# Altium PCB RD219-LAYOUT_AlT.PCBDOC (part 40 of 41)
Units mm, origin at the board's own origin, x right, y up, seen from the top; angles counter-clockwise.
Board outline 209.75 x 159.97 mm, 2 copper layers (TOP, BOTTOM), stack 0 mm thick; 398 components, 199 nets, 1469 pads, 0 vias.
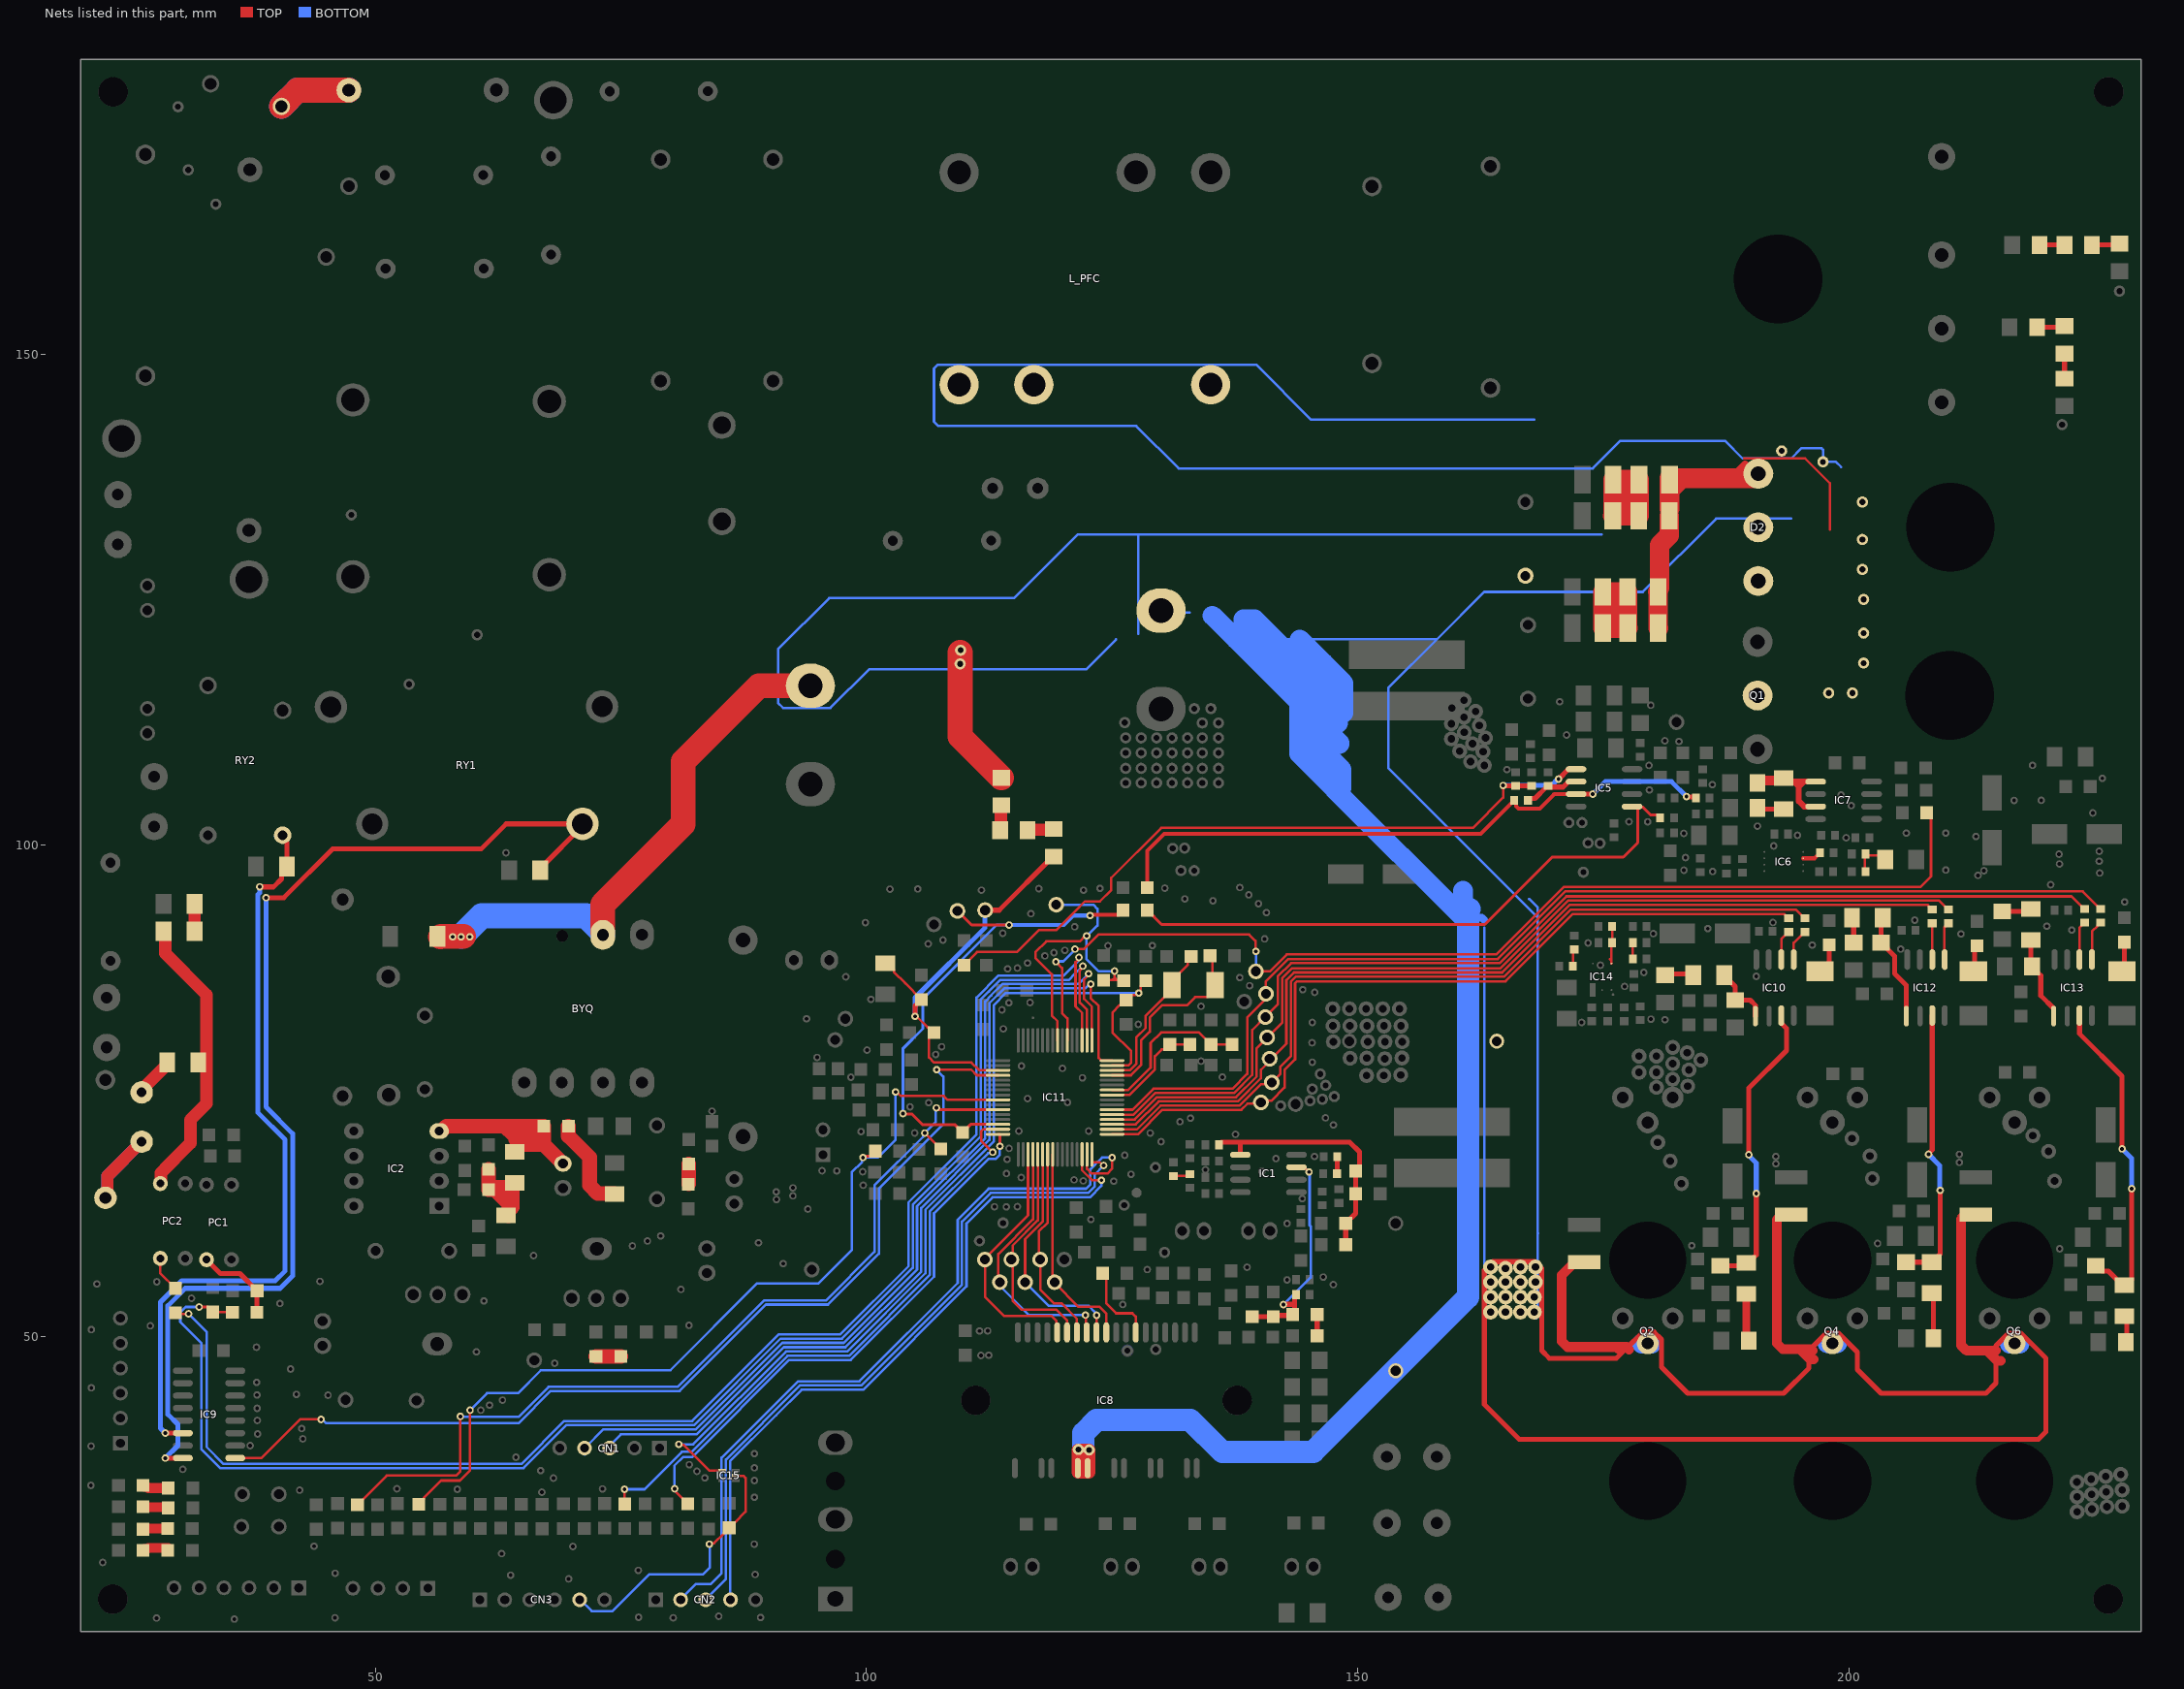
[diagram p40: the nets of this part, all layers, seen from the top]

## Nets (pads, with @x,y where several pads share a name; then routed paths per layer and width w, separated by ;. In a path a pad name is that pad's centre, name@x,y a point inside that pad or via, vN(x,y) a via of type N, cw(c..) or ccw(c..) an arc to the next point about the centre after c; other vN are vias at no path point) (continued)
NetD2_1: D2.1 D2.3 L_PFC.4 L_PFC.5 L_PFC.6 pad.@193.146,140.134 pad.@197.35,139.025 pad.@197.927,115.504 pad.@200.34,115.504 pad.@201.356,128.077 pad.@201.356,131.125 pad.@201.356,134.935 pad.@201.483,118.552 pad.@201.483,121.6 pad.@201.483,125.029 Q1.2 R37.2 R39.2 R94.1 R96.1 | length 208.2
  TOP w0.254: 189.313,139.38 195.514,139.38 198.054,136.84 198.054,132.141
  TOP w0.8: 187.894,137.348 188.021,137.348 189.418,138.745
  TOP w2: R96.1@180.554,125.791 180.567,125.778 180.567,122.121 R94.1@180.58,122.108 ; R96.1@180.704,126.191 180.704,130.539 181.697,131.532 R37.2@181.697,133.538 ; R39.2@181.71,136.117 R39.2@181.723,136.13 ; R37.2@181.723,134.225 R39.2@181.723,136.13 ; R39.2@181.723,137.221 R39.2@181.723,136.13 ; R39.2@181.723,137.348 182.941,137.348 ; 187.894,137.348 182.941,137.348 ; 188.021,137.348 D2.3@190.18,137.348 ; R39.2@181.723,136.13 182.941,137.348
  BOTTOM w0.254: 107.197,142.773 ccw(c107.391,142.936) 107.391,142.682 127.442,142.682 131.76,138.364 173.924,138.364 176.718,141.158 187.386,141.158 189.164,139.38 194.117,139.38 195.133,140.396 197.201,140.396 197.35,140.247 pad.@197.35,139.025 198.663,139.025 199.197,138.491 ; 107.196,142.773 106.868,143.101 106.868,148.524 107.249,148.905 139.678,148.905 145.266,143.317 167.955,143.317
NetD5_2: D5.2 R20.1 | length 9.8
  TOP w1.5: R20.1@69.657,71.435 69.657,70.419 71.816,68.26 71.816,65.402 72.645,64.573 74.306,64.573 D5.2@74.356,64.523
NetD8_2: D8.2 R15.2 R16.1 | length 4.6
  TOP w0.254: R16.1@201.613,97.343 R15.2@201.613,99.121 ; R15.2@201.675,99.121 201.802,98.994 D8.2@203.842,98.994 ; D8.2@203.234,98.127 D8.2@203.677,98.57
NetD11_1: D11.1 R44.2 | length 2.7
  TOP w0.5: R44.2@190.691,103.82 190.818,103.693 D11.1@193.355,103.693
NetD11_2: D11.2 IC7.5 IC7.7 R43.2 | length 11.4
  TOP w0.5: D11.2@193.555,106.849 D11.2@193.867,106.537
  TOP w0.6: D11.2@193.867,106.537 193.917,106.487 194.398,106.487 ; IC7.7@196.601,103.947 195.433,103.947 194.879,104.501 194.879,105.979 ; IC7.5@196.601,106.487 195.387,106.487 ; 194.398,106.487 194.879,106.487 ; 194.398,106.487 194.398,106.46 194.879,105.979 ; 194.879,105.979 195.387,106.487 ; 194.879,105.979 194.879,106.487 ; 194.879,106.487 195.387,106.487
  TOP w1.016: R43.2@190.691,106.36 190.936,106.605 193.111,106.605 D11.2@193.355,106.849
NetD12_1: D12.1 TH1.2 | length 4.4
  TOP w1.27: TH1.2@26.223,74.864 TH1.2@26.223,75.099 ; TH1.2@26.223,75.139 TH1.2@26.223,75.099 ; D12.1@28.836,77.912 28.836,77.712 TH1.2@26.223,75.099
  BOTTOM w1.27: TH1.2@26.223,74.864 TH1.2@26.498,74.864
NetD12_2: D12.2 PC2.C ZD3.2 | length 29.5
  TOP w1.27: PC2.C@28.128,65.593 28.177,65.642 28.177,66.666 28.915,67.416 30.41,68.933 31.176,69.709 31.176,72.07 32.827,73.721 32.827,84.805 28.62,89.012 28.62,91.082 ZD3.2@28.455,91.247
  BOTTOM w1.27: PC2.C@28.128,65.593 PC2.C@28.128,65.696
NetD14_1: D14.1 IC9.14 pad.@28.636,40.193 pad.@38.239,95.779 RY2.4 | length 77.3
  TOP w0.254: IC9.14@30.291,40.066 IC9.14@30.418,40.193
  TOP w0.5: pad.@28.636,40.193 IC9.14@30.418,40.193
  TOP w0.508: pad.@38.239,95.779 39.645,95.779 40.463,96.597 40.463,97.305 D14.1@41.009,97.851 41.009,100.257 40.574,100.692 RY2.4@40.574,101.036
  BOTTOM w0.254: RY2.4@39.812,100.909 RY2.4@39.939,100.909
  BOTTOM w0.5: pad.@28.636,40.193 28.128,40.701 28.128,53.528 30.287,55.687 39.812,55.687 40.828,56.703 40.828,70.038 38.071,72.795 38.071,95.011 38.239,95.179 pad.@38.239,95.779
NetD15_1: D15.1 R90.1 | length 4.3
  TOP w0.508: D15.1@197.038,87.183 D15.1@197.054,87.183 ; D15.1@197.8,87.929 D15.1@197.054,87.183 ; R90.1@197.993,89.861 197.993,87.929 197.247,87.183 D15.1@197.054,87.183
NetD16_1: D16.1 R91.2 | length 4.9
  TOP w0.8: D16.1@189.545,54.363 189.545,49.845 R91.2@189.799,49.591
NetD16_2: D16.2 IC10.7 pad.@189.801,68.519 pad.@190.561,64.577 R120.2 | length 30.5
  TOP w0.508: R120.2@187.005,57.211 D16.2@189.704,57.211 ; D16.2@189.545,57.519 189.745,57.519 190.291,58.065 190.561,58.335 pad.@190.561,64.577 ; pad.@189.801,68.519 189.801,75.293 193.636,79.128 193.636,81.372 193.101,81.907 IC10.7@193.101,82.682
  BOTTOM w0.508: pad.@189.801,68.519 189.801,68.45 190.561,67.69 pad.@190.561,64.577
NetD17_1: D17.1 R122.2 | length 2.9
  TOP w0.508: R122.2@181.29,86.802 181.417,86.929 D17.1@184.157,86.929
NetD17_2: D17.2 IC10.5 R123.2 | length 6.5
  TOP w0.508: D17.2@187.313,86.929 187.313,86.729 D17.2@187.859,86.183 ; D17.2@187.859,86.183 188.402,85.64 R123.2@188.402,84.262 189.926,84.262 190.462,83.726 190.462,82.636 IC10.5@190.466,82.632
NetD18_1: D18.1 R125.1 | length 2.7
  TOP w0.508: D18.1@212.659,87.183 212.786,87.31 R125.1@212.786,89.85
NetD19_1: D19.1 R126.2 | length 4.7
  TOP w0.508: D19.1@208.414,54.436 208.595,54.255 R126.2@208.595,49.845
NetD19_2: D19.2 IC12.7 pad.@208.087,68.559 pad.@209.275,64.897 R127.2 | length 28.8
  TOP w0.508: R127.2@205.801,57.592 D19.2@208.414,57.592 208.614,57.592 209.16,58.138 209.16,58.321 209.275,58.436 pad.@209.275,64.897 ; pad.@208.087,68.559 208.087,68.628 208.468,69.009 IC12.7@208.468,82.682
  BOTTOM w0.508: pad.@208.087,68.559 209.239,67.407 209.239,64.933 pad.@209.275,64.897
NetD21_1: D21.1 R129.2 | length 2.6
  TOP w0.508: D21.1@200.286,92.644 200.467,92.463 R129.2@200.467,90.107
NetD21_2: D21.2 IC12.5 R130.2 | length 11.2
  TOP w0.508: D21.2@203.442,92.644 203.261,92.463 R130.2@203.261,90.104 203.361,90.104 203.907,89.558 203.907,89.458 204.625,88.74 204.625,86.962 205.833,85.754 IC12.5@205.833,82.632
NetD22_1: D22.1 R132.1 | length 3.7
  TOP w0.508: D22.1@227.772,86.857 227.899,86.984 227.899,87.111 D22.1@228.153,87.365 ; D22.1@227.772,87.183 228.026,87.437 R132.1@228.026,90.155
NetD23_1: D23.1 R137.2 | length 2.8
  TOP w0.508: D23.1@227.899,52.004 228.28,51.623 R137.2@228.28,49.337
NetD23_2: D23.2 IC13.7 pad.@227.792,69.117 pad.@228.767,65.064 R138.1 | length 33.4
  TOP w0.508: IC13.7@223.454,82.682 223.454,80.833 227.772,76.515 pad.@227.772,69.149 ; R138.1@224.851,57.211 R138.1@224.951,57.211 ; R138.1@225.332,57.087 225.751,56.668 226.391,56.668 D23.2@227.899,55.16 ; D23.2@228.026,55.233 228.226,55.233 228.772,55.779 228.772,64.942 pad.@228.788,64.958
  BOTTOM w0.508: pad.@227.792,69.117 228.767,68.141 pad.@228.767,65.064
NetD24_1: D24.1 R140.2 | length 3
  TOP w0.508: R140.2@215.58,93.279 218.247,93.279 D24.1@218.501,93.533
NetD24_2: D24.2 IC13.5 R141.1 | length 8.7
  TOP w0.508: D24.2@218.501,90.377 218.501,87.821 R141.1@218.631,87.691 218.631,87.591 219.177,87.045 219.219,87.045 219.517,86.747 219.517,84.726 220.819,83.424 IC13.5@220.819,82.632
NetEC3_1: EC3.1 IC2.4 R20.2 ZD1.2 | length 25.9
  TOP w1.27: EC3.1@69.105,67.625 EC3.1@69.272,67.625
  TOP w1.5: IC2.4@56.513,70.927 56.74,70.927 57.248,71.435 63.18,71.435 ; ZD1.2@64.196,69.022 ZD1.2@64.768,69.594 ; 65.203,70.478 64.323,70.478 ; EC3.1@69.105,67.625 69.083,67.625 67.168,69.54 ; 63.18,71.435 64.323,71.435 ; 63.18,71.435 64.137,70.478 64.323,70.478 ; 64.323,70.478 64.323,71.435 ; 64.323,70.478 64.323,70.038 ZD1.2@64.768,69.594 ; 64.323,71.435 R20.2@66.609,71.435 ; ZD1.2@64.768,69.594 R20.2@66.609,71.435 ; ZD1.2@64.768,69.594 64.821,69.54 67.168,69.54 ; R20.2@66.609,71.435 R20.2@67.168,71.435 67.168,69.54
NetFB1_1: FB1.1 R82.2 | length 2
  TOP w1.5: FB1.1@81.904,65.557 R82.2@81.904,67.578
NetIC1_3: IC1.3 pad.@142.428,53.274 pad.@145.035,66.77 R55.2 R56.1 R58.2 R83.2 | length 23.9
  TOP w0.254: IC1.3@143.754,67.244 144.533,67.244 145.007,66.77 pad.@145.035,66.77
  TOP w0.508: R56.1@139.253,52.055 R55.2@141.412,52.055 141.514,52.156 143.266,52.156 R58.2@143.368,52.258 143.552,52.442 143.552,53.293 ; pad.@142.477,53.149 142.477,53.225 pad.@142.428,53.274 142.447,53.293 143.552,53.293 ; R83.2@143.698,54.29 143.552,54.144 143.552,53.293
  BOTTOM w0.254: pad.@142.428,53.274 142.453,53.274 145.203,56.024 145.203,61.229 145.095,61.337 145.095,66.71 pad.@145.035,66.77
NetIC1_5: IC1.5 R45.2 R97.2 R98.1 R99.2 R100.2 | length 26.1
  TOP w0.254: R99.2@149.788,66.857 R99.2@149.794,66.863
  TOP w0.508: R45.2@135.889,69.53 135.889,69.58 136.035,69.726 136.085,69.726 136.143,69.784 137.983,69.784 ; IC1.5@138.054,68.514 138.054,69.713 137.983,69.784 ; R97.2@148.778,59.37 R98.1@148.778,61.529 149.788,62.539 R100.2@149.788,64.548 149.791,64.551 149.791,66.854 R99.2@149.788,66.857 ; R99.2@149.794,66.863 150.175,67.244 150.175,68.814 149.205,69.784 137.983,69.784
NetIC5_1: IC5.1 R33.2 R34.1 | length 61.2
  TOP w0.3: R34.1@128.585,93.406 130.04,91.951 162.928,91.951 169.774,98.797 177.029,98.797 178.496,100.264 178.496,103.82 IC5.1@178.566,103.89 ; IC5.1@177.917,103.947 IC5.1@178.496,103.947 ; R33.2@180.779,102.804 180.779,102.854 180.529,103.104 179.801,103.104 179.015,103.89 IC5.1@178.566,103.89 ; IC5.1@178.496,103.947 178.623,103.947 IC5.1@178.566,103.89 ; IC5.1@178.496,103.947 178.553,103.89 IC5.1@178.566,103.89
NetIC5_5: IC5.5 pad.@164.799,106.092 pad.@170.428,106.744 R4.2 R7.2 R8.1 | length 75
  TOP w0.254: R7.2@109.916,87.818 111.254,89.156 115.318,89.156 117.536,91.374 119.314,91.374 121.283,93.343 122.232,94.292 123.756,94.292 124.902,95.438 124.902,96.708 129.982,101.788 161.732,101.788 164.799,104.855 pad.@164.799,106.092
  TOP w0.508: pad.@164.799,106.092 164.824,106.066 166.025,106.066 R8.1@166.05,106.041 R4.2@167.701,106.041 ; pad.@170.428,106.744 170.441,106.744 171.454,107.757 IC5.5@172.217,107.757
  BOTTOM w0.508: pad.@164.799,106.092 169.707,106.092 170.359,106.744 pad.@170.428,106.744
NetIC5_6: IC5.6 R5.2 R6.1 | length 5.9
  TOP w0.508: R6.1@167.32,104.582 167.32,104.632 167.466,104.778 168.039,104.778 169.192,105.931 R5.2@169.462,105.931 ; R5.2@169.352,106.041 R5.2@169.462,105.931 ; IC5.6@172.217,106.487 171.442,106.487 170.886,105.931 R5.2@169.462,105.931
NetIC5_7: IC5.7 pad.@173.924,105.217 pad.@183.449,104.963 R6.2 R9.1 R10.2 | length 64.9
  TOP w0.254: R9.1@128.585,95.692 R9.1@129.108,96.215
  TOP w0.4: R9.1@128.585,95.692 128.585,99.447 130.291,101.153 162.491,101.153 165.67,104.332 165.72,104.332 165.92,104.532 R6.2@165.92,104.582 166.12,104.382 166.12,103.988 166.354,103.754 168.524,103.754 169.987,105.217 IC5.7@172.217,105.217
  TOP w0.508: IC5.7@172.217,105.217 pad.@173.924,105.217 ; pad.@183.449,104.963 183.498,104.914 184.322,104.914 R10.2@184.4,104.836 R10.2@184.365,104.801
  BOTTOM w0.508: pad.@173.924,105.217 175.194,106.487 181.925,106.487 pad.@183.449,104.963
NetIC8_7: IC8.7 R50.1 | length 8.2
  TOP w0.254: R50.1@124.445,56.449 124.394,56.398 124.394,53.401 125.41,52.385 127.061,52.385 127.406,52.04 IC8.7@127.406,50.437
NetIC10_1: IC10.1 R84.2 | length 3.3
  TOP w0.254: IC10.1@194.371,88.382 194.371,90.089 195.464,91.182 R84.2@195.514,91.182
NetIC10_2: IC10.2 R87.2 | length 3.1
  TOP w0.254: IC10.2@193.101,88.382 193.101,90.47 193.813,91.182 R87.2@193.863,91.182
NetIC12_1: IC12.1 R85.2 | length 3.9
  TOP w0.254: IC12.1@209.738,88.382 209.716,88.404 209.716,91.649 209.796,91.729 209.796,91.798 210.069,92.071 R85.2@210.119,92.071
NetIC12_2: IC12.2 R88.2 | length 3.7
  TOP w0.254: R88.2@208.418,92.071 R88.2@208.468,92.071 IC12.2@208.468,88.382
NetIC13_1: IC13.1 R86.2 | length 4.2
  TOP w0.254: IC13.1@224.724,88.382 224.724,91.247 225.29,91.813 225.29,91.863 225.563,92.136 R86.2@225.613,92.136
NetIC13_2: IC13.2 R89.2 | length 4
  TOP w0.254: IC13.2@223.454,88.382 223.454,91.628 223.639,91.813 223.639,91.863 223.912,92.136 R89.2@223.962,92.136
NetIC14_4: IC14.4 pad.@175.894,91.705 R92.2 R93.1 | length 4.4
  TOP w0.254: R93.1@175.621,92.028 R93.1@175.894,91.755 pad.@175.894,91.705 R92.2@175.894,90.104 175.824,90.034 175.824,88.249 ; 175.667,88.407 175.824,88.249 ; IC14.4@175.824,87.978 175.824,88.249
NetLED1_2: LED1.2 R67.1 | length 2.7
  TOP w1: LED1.2@26.35,28.255 26.5,28.405 26.8,28.405 26.904,28.509 R67.1@28.941,28.509
NetLED2_2: LED2.2 R68.1 | length 2.6
  TOP w1: LED2.2@26.35,30.414 26.414,30.478 R68.1@28.877,30.478 R68.1@28.941,30.541
NetLED3_2: LED3.2 R69.1 | length 2.6
  TOP w1: LED3.2@26.35,32.7 26.414,32.637 28.877,32.637 R69.1@28.941,32.573
NetLED4_2: LED4.2 R70.1 | length 2.7
  TOP w1: LED4.2@26.35,34.859 26.5,34.709 26.8,34.709 26.904,34.605 R70.1@28.941,34.605
NetLED5_2: LED5.2 R136.1 | length 2.5
  TOP w1.5: R136.1@72.451,47.991 LED5.2@74.991,47.991
NetPC1_E: PC1.E R48.2 R49.2 | length 8.7
  TOP w0.5: PC1.E@32.827,57.846 PC1.E@32.979,57.694
  TOP w0.508: PC1.E@32.979,57.694 34.237,56.436 36.218,56.436 R49.2@37.983,54.671 37.969,54.657 37.969,52.489 R48.2@37.955,52.475
NetPC2_A: PC2.A R47.2 | length 3.7
  TOP w0.254: PC2.A@28.128,57.973 28.128,56.449 R47.2@29.652,54.925
  TOP w0.5: PC2.A@28.128,57.973 PC2.A@28.153,57.948
NetR21_2: R21.2 R22.2 ZD1.1 ZD2.1 | length 11.4
  TOP w1.5: R21.2@61.529,67.041 R22.2@61.529,64.958 ; ZD2.1@63.557,62.295 63.307,62.545 63.946,63.184 ; ZD1.1@64.196,65.466 ZD1.1@63.946,65.216 ; R22.2@61.529,64.958 62.172,64.958 63.946,63.184 ; R22.2@61.529,64.958 61.787,65.216 ZD1.1@63.946,65.216 ; 63.946,63.184 ZD1.1@63.946,65.216
NetR23_2: R23.2 R24.1 | length 2.8
  TOP w0.508: R23.2@219.139,152.715 221.803,152.715 R24.1@221.93,152.842
NetR24_2: R24.2 R25.1 | length 2.5
  TOP w0.508: R25.1@221.93,147.508 R24.2@221.93,150.042
NetR26_2: R26.2 R27.1 | length 2.5
  TOP w0.508: R26.2@219.393,161.097 R27.1@221.927,161.097
NetR27_2: R27.2 R28.1 | length 2.8
  TOP w0.508: R27.2@224.727,161.097 227.391,161.097 R28.1@227.518,161.224
NetR37_1: R37.1 R38.2 R39.1 R40.2 | length 16.5
  TOP w2: 177.353,133.538 R37.1@178.597,133.538 178.61,133.551 178.61,137.208 R39.1@178.623,137.221 177.607,137.221 ; 177.353,133.538 177.607,133.792 177.607,137.221 ; 177.353,133.538 R38.2@175.956,133.538 175.969,133.551 175.969,137.208 R40.2@175.982,137.221 177.607,137.221
NetR57_2: R57.2 R58.1 | length 2.2
  TOP w0.508: R57.2@145.857,50.099 R58.1@145.857,52.258
NetR63_1: R63.1 R64.2 | length 2.6
  TOP w1.27: R64.2@113.596,101.534 113.661,101.599 113.661,104.006 R63.1@113.726,104.071
NetR64_1: R64.1 R65.2 | length 2.7
  TOP w1.27: R64.1@116.396,101.534 116.46,101.598 118.997,101.598 R65.2@119.06,101.661
NetR94_2: R94.2 R96.2 R104.1 R105.1 | length 16.2
  TOP w2: R94.2@177.48,122.108 R94.2@177.467,122.121 ; 176.337,122.108 177.454,122.108 R94.2@177.467,122.121 ; 176.337,122.108 176.464,122.235 176.464,125.791 ; 176.337,122.108 R105.1@174.94,122.108 R104.1@174.94,125.791 176.464,125.791 ; 176.464,125.791 R96.2@177.454,125.791 177.467,125.778 R94.2@177.467,122.121
NetR101_1: R101.1 R102.2 | length 1.8
  TOP w0.254: R102.2@171.892,87.691 171.892,89.277 R101.1@172.019,89.404
NetR107_1: R107.1 TH1.1 | length 14.7
  TOP w1.27: R107.1@22.54,64.134 22.734,64.328 22.734,66.357 TH1.1@26.223,69.846
  BOTTOM w1.27: R107.1@22.54,64.134 22.734,64.328 22.734,66.357 TH1.1@26.223,69.846 TH1.1@26.029,70.04
NetR110_1: R110.1 R115.2 | length 1.8
  TOP w0.254: R110.1@147.889,66.659 R110.1@147.889,66.609 R110.1@147.892,66.612
  TOP w0.508: R110.1@147.892,66.612 147.9,66.62 147.9,68.307 R115.2@147.911,68.318
NetR114_2: R114.2 R117.1 | length 1.7
  TOP w0.254: R117.1@131.252,66.352 132.773,66.352 R114.2@132.903,66.482
NetR145_1: R145.1 R146.2 | length 1.7
  TOP w0.254: R146.2@177.985,88.453 R145.1@177.985,90.104
NetSA1_2: SA1.2 Z3.1 | length 15.1
  TOP w2.54: Z3.1@40.447,175.194 42.098,176.845 SA1.2@47.305,176.845
  BOTTOM w2.54: Z3.1@40.447,175.194 42.098,176.845 SA1.2@47.305,176.845
NetZD3_1: ZD3.1 ZD9.2 | length 2.8
  TOP w1.27: ZD3.1@31.611,91.247 ZD9.2@31.611,94.041
OUTPIPE: C70.1 IC11.25 pad.@59.646,42.53 pad.@99.642,68.236 pad.@102.953,74.907 R73.2 | length 89.6
  TOP w0.254: R73.2@54.417,32.954 54.94,33.477 54.94,33.604 56.703,35.367 58.608,35.367 59.646,36.405 pad.@59.646,42.53 ; pad.@99.642,68.236 99.78,68.236 99.916,68.372 100.376,68.372 C70.1@100.899,68.895 ; pad.@102.953,74.907 103.09,74.907 103.49,74.508 107.859,74.508 108.265,74.102 113.383,74.102 IC11.25@113.387,74.106
  BOTTOM w0.254: pad.@59.646,42.53 61.373,44.257 64.522,44.257 66.855,46.59 80.032,46.59 88.875,55.433 95.105,55.433 98.486,58.814 98.486,66.736 99.545,67.795 99.545,68.139 pad.@99.642,68.236 101.129,68.236 102.953,70.06 pad.@102.953,74.907
OUTROOM: C69.1 IC11.27 pad.@58.656,41.895 pad.@105.929,70.725 pad.@107.11,73.289 R71.2 | length 92.5
  TOP w0.254: R71.2@48.194,32.903 51.166,35.875 58.227,35.875 58.656,36.304 pad.@58.656,41.895 ; pad.@105.929,70.725 105.929,70.718 C69.1@107.55,69.097 ; pad.@107.11,73.289 107.205,73.289 107.388,73.106 IC11.27@113.387,73.106
  BOTTOM w0.254: pad.@58.656,41.895 58.707,41.844 64.601,41.844 67.651,44.894 80.78,44.894 89.591,53.705 95.893,53.705 100.82,58.632 100.82,65.387 105.759,70.326 105.759,70.418 105.929,70.588 pad.@105.929,70.725 107.053,71.849 107.053,73.232 pad.@107.11,73.289
PFC_BRK: IC6.7 R151.1 | length 2
  TOP w0.4: IC6.7@195.33,98.684 196.521,98.684 197.035,99.198 R151.1@197.035,99.248
PFC_FO: C19.1 IC11.8 pad.@122.408,90.795 pad.@125.249,87.205 R17.2 TP6.1 | length 33.4
  TOP w0.254: IC11.8@119.437,80.156 119.437,82.107 118.869,82.675 118.869,86.866 117.195,88.54 117.195,89.128 118.298,90.231 121.714,90.231 pad.@122.278,90.795 ; pad.@122.408,90.795 pad.@122.545,90.795 ; C19.1@124.148,86.291 124.992,86.291 ; 125.249,86.406 125.249,86.548 ; pad.@125.249,87.205 125.249,86.548 ; 125.461,86.337 125.459,86.337 125.249,86.548 ; R17.2@126.065,86.202 R17.2@126.348,85.919 ; R17.2@126.119,86.291 124.992,86.291 ; R17.2@126.281,85.852 R17.2@126.348,85.919 ; R17.2@126.51,85.758 R17.2@126.348,85.919 ; 124.992,86.291 125.249,86.548
  BOTTOM w0.254: TP6.1@119.314,93.66 TP6.1@119.376,93.598 ; TP6.1@119.314,93.954 123.084,93.954 123.505,93.533 123.505,91.831 122.469,90.795 pad.@122.408,90.795 122.362,90.749 122.362,88.453 123.61,87.205 pad.@125.249,87.205
PFC_PWM: IC11.6 pad.@119.276,88.162 pad.@121.212,89.446 pad.@139.634,89.215 R41.1 TP8.1 | length 112.7
  TOP w0.254: pad.@119.276,88.162 119.276,88.149 119.898,87.527 119.898,82.916 120.437,82.377 IC11.6@120.437,80.156 ; pad.@121.212,89.446 122.132,89.446 123.612,90.926 138.939,90.926 139.583,90.282 139.583,89.266 pad.@139.634,89.215 ; TP8.1@139.634,87.183 141.031,87.183 142.758,88.91 164.094,88.91 170.952,95.768 207.274,95.768 208.341,96.835 208.341,102.88 R41.1@207.909,103.312
  BOTTOM w0.254: pad.@119.276,88.162 119.317,88.203 120.038,88.203 121.212,89.377 pad.@121.212,89.446 ; TP8.1@139.634,87.183 pad.@139.634,89.215
PTC: IC9.1 IC11.20 pad.@44.482,41.59 pad.@107.137,77.174 | length 102.7
  TOP w0.254: IC9.1@35.748,37.653 38.41,37.653 42.376,41.62 44.453,41.62 pad.@44.482,41.59 ; pad.@107.137,77.174 110.654,77.174 111.222,76.606 IC11.20@113.387,76.606
  BOTTOM w0.254: pad.@44.482,41.59 44.62,41.59 45.001,41.209 64.577,41.209 67.838,44.47 80.967,44.47 89.77,53.273 96.072,53.273 101.252,58.453 101.252,65.057 107.811,71.616 107.811,76.461 107.137,77.135 pad.@107.137,77.174
PTC-O: D1.1 IC9.16 pad.@28.636,37.653 pad.@38.88,94.676 RY1.4 | length 113.2
  TOP w0.5: pad.@28.636,37.653 IC9.16@30.418,37.653 ; pad.@38.88,94.676 40.701,94.676 45.654,99.629 60.767,99.629 63.326,102.187 RY1.4@71.088,102.187 71.088,101.968 D1.1@66.9,97.78
  BOTTOM w0.5: pad.@28.636,37.653 29.906,38.923 29.906,41.082 28.89,42.098 28.89,53.147 30.668,54.925 40.32,54.925 41.59,56.195 41.59,70.673 38.88,73.383 pad.@38.88,94.676
PWM_UH0: IC8.15 IC11.35 TP16.1 | length 25.8
  TOP w0.254: TP16.1@112.046,57.846 112.046,57.978 116.437,62.369 IC11.35@116.437,68.556 ; TP16.1@112.075,57.817 112.075,54.036 113.98,52.131 118.806,52.131 119.34,51.597 119.34,50.503 IC8.15@119.406,50.437
PWM_UH1: IC11.49 R87.1 TP23.1 | length 83.9
  TOP w0.254: IC11.49@124.987,70.606 127.629,70.606 130.108,73.085 138.145,73.085 138.781,73.721 139.772,73.721 139.899,73.848 TP23.1@140.142,73.848 140.307,74.013 141.196,74.013 142.555,75.372 142.555,77.15 143.622,78.217 143.622,85.964 143.825,86.167 165.025,86.167 171.883,93.025 193.391,93.025 193.54,92.876 193.54,92.855 193.813,92.582 R87.1@193.863,92.582
PWM_UL0: IC8.12 IC11.36 pad.@122.285,52.201 TP19.1 | length 26.8
  TOP w0.254: TP19.1@113.559,55.56 113.415,55.704 113.415,58.424 116.937,61.946 IC11.36@116.937,68.556 ; pad.@122.285,52.201 122.346,52.141 122.346,50.497 IC8.12@122.406,50.437
  BOTTOM w0.254: TP19.1@113.178,55.56 113.369,55.37 116.537,52.201 pad.@122.285,52.201
PWM_UL1: IC11.50 R84.1 TP26.1 | length 85
  TOP w0.254: IC11.50@124.987,71.106 127.518,71.106 129.929,73.517 137.966,73.517 140.125,75.675 141.051,75.675 TP26.1@141.256,75.88 142.123,76.747 142.123,77.48 143.19,78.547 143.19,86.143 143.677,86.63 164.878,86.63 171.704,93.457 194.589,93.457 195.464,92.582 R84.1@195.514,92.582
PWM_VH0: IC8.14 IC11.37 TP17.1 | length 23.7
  TOP w0.254: IC11.37@117.437,68.556 117.437,61.835 114.883,59.281 114.883,57.987 TP17.1@114.742,57.846 114.873,57.715 114.873,53.651 115.758,52.766 119.314,52.766 120.406,51.674 IC8.14@120.406,50.437
PWM_VH1: IC11.51 R88.1 TP24.1 | length 97.4
  TOP w0.254: IC11.51@124.987,71.606 127.407,71.606 129.75,73.949 137.787,73.949 140.142,76.304 140.142,77.15 141.031,78.039 TP24.1@141.031,78.293 141.212,78.293 142.733,79.814 142.733,86.297 143.498,87.062 164.699,87.062 171.585,93.949 207.99,93.949 208.145,93.794 208.145,93.744 208.418,93.471 R88.1@208.468,93.471
PWM_VL0: IC8.11 IC11.38 pad.@123.417,52.182 TP20.1 | length 24.3
  TOP w0.254: TP20.1@116.139,55.56 116.139,59.926 117.937,61.724 IC11.38@117.937,68.556 ; IC8.11@123.406,50.437 123.411,50.442 123.411,52.176 pad.@123.417,52.182
  BOTTOM w0.254: TP20.1@116.139,55.56 118.564,53.135 122.628,53.135 123.214,52.549 123.214,52.522 123.417,52.319 pad.@123.417,52.182
PWM_VL1: IC11.52 R85.1 TP27.1 | length 99.1
  TOP w0.254: IC11.52@124.987,72.106 127.296,72.106 129.571,74.381 137.608,74.381 139.71,76.483 139.71,79.365 140.777,80.432 TP27.1@140.777,80.452 140.797,80.452 142.301,81.956 142.301,86.476 143.319,87.494 164.52,87.494 171.406,94.381 209.159,94.381 210.069,93.471 R85.1@210.119,93.471
PWM_WH0: IC8.13 IC11.39 TP18.1 | length 20.5
  TOP w0.254: IC11.39@118.437,68.556 118.437,61.613 117.536,60.712 117.536,57.987 TP18.1@117.677,57.846 117.677,54.784 119.06,53.401 119.822,53.401 121.406,51.817 IC8.13@121.406,50.437
PWM_WH1: IC11.53 R89.1 TP25.1 | length 113
  TOP w0.254: IC11.53@124.987,72.606 127.185,72.606 129.392,74.813 137.429,74.813 139.253,76.637 139.253,81.214 140.578,82.539 141.863,83.824 141.863,86.649 143.224,88.01 164.425,88.01 171.228,94.813 222.635,94.813 R89.1@223.912,93.536
PWM_WL0: IC8.10 IC11.40 TP21.1 | length 21.6
  TOP w0.254: IC11.40@118.937,68.556 118.946,68.547 118.946,55.761 TP21.1@119.147,55.56 119.147,55.473 121.584,53.036 123.727,53.036 124.406,52.357 IC8.10@124.406,50.437
PWM_WL1: IC11.54 R86.1 TP28.1 | length 114.9
  TOP w0.254: IC11.54@124.987,73.106 127.074,73.106 129.213,75.245 137.251,75.245 138.745,76.739 138.745,82.484 140.392,84.131 140.392,84.725 TP28.1@140.564,84.897 ; TP28.1@140.65,84.897 140.65,86.167 142.925,88.442 164.246,88.442 171.115,95.311 223.788,95.311 R86.1@225.563,93.536
RESET: C38.2 IC11.63 IC15.4 pad.@80.895,39.051 pad.@127.709,84.974 R81.1 | length 96.3
  TOP w0.254: pad.@80.895,39.051 80.957,38.989 81.402,38.989 84.016,36.375 IC15.4@85.325,36.375 ; IC11.63@124.987,77.606 126.628,77.606 126.934,77.912 126.934,79.055 125.029,80.96 125.029,82.992 125.776,83.739 125.903,83.739 C38.2@126.426,84.262 126.949,84.785 127.382,84.785 127.571,84.974 pad.@127.709,84.974 127.709,85.111 127.908,85.31 127.908,85.695 R81.1@128.431,86.218
  BOTTOM w0.254: pad.@80.895,39.051 82.358,39.051 91.805,48.498 98.035,48.498 106.004,56.467 106.004,62.92 112.94,69.856 112.94,83.73 114.184,84.974 pad.@127.709,84.974
RESETN: CN3.5 IC15.2 pad.@84.008,28.89 R150.1 | length 27.9
  TOP w0.254: pad.@84.008,28.89 84.102,28.984 84.483,28.984 85.504,30.005 85.504,30.032 R150.1@86.027,30.555 86.55,31.078 86.577,31.078 87.691,32.192 87.691,35.621 87.465,35.847 86.703,35.847 IC15.2@86.675,35.875
  BOTTOM w0.254: CN3.5@70.8,23.302 72.027,22.075 74.145,22.075 76.769,24.699 77.912,25.842 83.373,25.842 84.057,26.526 84.057,28.841 pad.@84.008,28.89 ; CN3.5@70.8,23.81 CN3.5@70.987,23.623
RXD0: IC11.32 pad.@80.475,34.534 pad.@113.576,69.379 R35.1 | length 56.5
  TOP w0.254: pad.@80.475,34.534 80.573,34.436 80.573,34.238 R35.1@81.813,32.997 ; IC11.32@113.387,70.606 113.555,70.606 113.576,70.585 pad.@113.576,69.379
  BOTTOM w0.254: pad.@80.452,34.768 80.452,36.891 81.341,37.78 82.286,37.78 92.14,47.634 98.393,47.634 106.868,56.109 106.868,62.562 107.884,63.578 112.401,68.095 113.135,68.095 113.555,68.515 113.555,69.358 pad.@113.576,69.379
RXD2: C30.1 IC11.2 pad.@32.071,53.026 pad.@122.017,87.718 R48.1 | length 153
  TOP w0.254: pad.@32.071,53.026 32.948,53.026 C30.1@33.462,52.512 35.429,52.512 R48.1@35.466,52.475 ; R48.1@35.137,52.01 35.534,52.407 R48.1@35.739,52.612 ; pad.@122.017,87.718 122.017,87.58 121.702,87.265 121.702,84.008 122.437,83.273 IC11.2@122.437,80.156
  BOTTOM w0.254: pad.@32.071,53.026 30.718,53.026 30.16,52.467 30.16,51.496 32.319,49.337 32.319,38.542 34.224,36.637 65.085,36.637 69.446,40.998 82.45,40.998 91.256,49.804 97.496,49.804 104.708,57.015 104.708,63.457 111.619,70.368 111.619,84.289 112.456,85.127 112.456,85.151 113.624,86.319 120.619,86.319 121.195,86.895 pad.@122.017,87.718
SCLK: CN2.3 IC11.48 pad.@124.133,67.425 | length 72.5
  TOP w0.254: IC11.48@122.937,68.556 122.937,67.773 122.958,67.752 123.73,67.752 124.057,67.425 pad.@124.133,67.425
  BOTTOM w0.254: CN2.3@83.627,23.302 85.685,25.36 85.685,37.508 93.219,45.042 99.466,45.042 109.713,55.289 109.713,61.707 112.634,64.628 122.54,64.628 123.225,65.313 123.225,66.517 pad.@124.133,67.425
SDIN: CN2.2 IC11.47 pad.@124.994,68.228 | length 79.6
  TOP w0.254: IC11.47@122.437,68.556 122.437,67.064 122.892,66.609 124.513,66.609 124.994,67.09 pad.@124.994,68.228
  BOTTOM w0.254: CN2.2@81.087,23.302 82.633,24.848 84.157,24.848 85.253,25.944 85.253,37.687 93.04,45.474 99.287,45.474 109.281,55.468 109.281,61.91 112.431,65.06 122.337,65.06 122.793,65.516 122.793,67.04 123.251,67.498 123.251,67.513 123.966,68.228 pad.@124.994,68.228
SWCLK: CN1.3 IC11.64 pad.@122.82,85.882 | length 89.9
  TOP w0.254: pad.@122.82,85.882 122.82,84.461 123.632,83.649 123.632,78.361 123.887,78.106 IC11.64@124.987,78.106
  BOTTOM w0.254: CN1.3@73.848,38.669 73.848,38.923 74.991,40.066 82.717,40.066 91.581,48.93 97.856,48.93 105.572,56.646 105.572,63.099 112.508,70.035 112.508,83.933 114.03,85.455 122.255,85.455 122.683,85.882 pad.@122.82,85.882
SWDIO: CN1.4 IC11.1 pad.@122.601,86.935 | length 90.9
  TOP w0.254: pad.@122.601,86.935 122.601,86.797 122.134,86.331 122.134,84.389 122.937,83.586 IC11.1@122.937,80.156
  BOTTOM w0.254: CN1.4@71.308,38.034 CN1.4@71.626,38.351 ; CN1.4@71.308,38.796 71.435,38.796 73.213,40.574 82.626,40.574 91.431,49.38 97.695,49.38 105.14,56.825 105.14,63.278 112.075,70.213 112.075,70.673 112.076,70.674 112.076,84.112 112.71,84.746 112.71,84.77 113.827,85.887 121.553,85.887 pad.@122.601,86.935
SYNC: CN2.4 IC11.46 pad.@123.911,65.923 | length 71.8
  TOP w0.254: IC11.46@121.937,68.556 121.937,66.953 122.95,65.94 123.894,65.94 pad.@123.911,65.923
  BOTTOM w0.254: CN2.4@86.167,23.302 86.117,23.352 86.117,37.329 90.79,42.002 93.398,44.61 99.645,44.61 110.17,55.135 110.17,61.529 112.837,64.196 122.743,64.196 123.906,65.359 123.906,65.918 pad.@123.911,65.923
TXD0: IC11.31 pad.@75.372,34.478 pad.@112.851,68.781 R36.1 | length 61.4
  TOP w0.254: pad.@75.372,34.478 75.372,33 R36.1@75.403,32.969 ; pad.@112.851,68.781 112.824,68.781 111.694,69.911 111.694,70.927 111.873,71.106 IC11.31@113.387,71.106
  BOTTOM w0.254: pad.@75.372,34.478 77.404,34.478 81.214,38.288 82.195,38.288 91.973,48.066 98.214,48.066 106.436,56.288 106.436,62.741 111.347,67.652 112.379,68.684 112.754,68.684 pad.@112.851,68.781
TXD2: IC11.3 pad.@31.001,52.33 pad.@121.624,88.601 R47.1 | length 147.6
  TOP w0.254: R47.1@29.652,52.436 29.757,52.33 pad.@31.001,52.33 ; pad.@121.624,88.601 121.624,88.463 121.27,88.109 121.27,83.627 121.937,82.96 IC11.3@121.937,80.156
  BOTTOM w0.254: pad.@31.001,52.33 32.827,50.504 32.827,38.796 34.562,37.061 64.874,37.061 69.235,41.422 82.268,41.422 91.095,50.249 97.342,50.249 104.276,57.183 104.276,63.66 111.187,70.571 111.187,84.517 113.421,86.751 120.067,86.751 120.797,87.481 121.527,88.21 121.527,88.503 pad.@121.624,88.601
VAC_AD: C28.1 IC11.30 pad.@103.705,72.706 pad.@114.506,91.891 pad.@122.752,92.862 R34.2 TP7.1 | length 53.3
  TOP w0.3: pad.@103.705,72.706 103.73,72.681 104.606,72.681 105.725,71.562 109.027,71.562 C28.1@109.789,70.8 110.595,71.606 IC11.30@113.387,71.606 ; TP7.1@109.258,93.325 110.693,91.891 pad.@114.506,91.891
  TOP w0.4: pad.@122.752,92.862 122.85,92.862 122.944,92.956 125.646,92.956 R34.2@126.096,93.406
  BOTTOM w0.3: pad.@103.705,72.706 103.693,72.718 103.693,79.309 105.725,81.341 105.725,84.389 113.227,91.891 pad.@114.506,91.891
  BOTTOM w0.4: pad.@114.506,91.891 120.085,91.891 121.056,92.862 pad.@122.752,92.862
VBB: BYQ.2 C10.2 C55.2 C90.2 C101.1 C102.1 C103.1 D2.2 D3.2 EC1.1 EC2.1 IC8.23 IC8.24 pad.@57.878,90.695 pad.@58.735,90.695 pad.@59.624,90.695 pad.@109.58,119.856 pad.@109.527,118.469 pad.@121.558,38.531 pad.@122.655,38.475 pad.@163.51,52.512 pad.@163.51,54.036 pad.@163.51,55.56 pad.@163.51,57.084 pad.@165.034,52.512 pad.@165.034,54.036 pad.@165.034,55.56 pad.@165.034,56.957 pad.@166.558,52.512 pad.@166.558,54.036 pad.@166.558,55.56 pad.@166.558,57.084 pad.@167.955,52.512 pad.@167.955,54.036 pad.@168.32,60.526 pad.@168.082,55.56 pad.@168.082,57.084 Q2.2 Q4.2 Q6.2 R63.2 | length 857.8
  TOP w0.508: pad.@163.51,52.341 pad.@163.51,52.512 ; 176.21,48.956 176.21,48.738 176.736,48.212 ; 176.736,48.212 177.417,48.893 179.004,50.48 180.147,50.48 180.909,49.718 180.909,46.924 183.576,44.257 193.355,44.257 195.895,46.797 195.895,47.849 195.895,48.575 196.058,48.738 197.673,50.353 198.943,50.353 200.848,48.448 200.848,46.67 203.261,44.257 213.929,44.257 214.945,45.273 214.945,47.686 214.945,48.575 214.945,49.083 216.215,50.353 217.485,50.353 220.025,47.813 220.025,40.32 219.263,39.558 166.431,39.558 162.875,43.114 162.875,52.512 162.875,56.777 163.734,57.636 166.558,57.636 168.038,57.636 168.336,57.338 168.717,56.957 168.717,48.588 169.492,47.813 176.337,47.813 176.736,48.212
  TOP w1: C101.1@173.035,57.597 172.835,57.397 171.885,57.397 170.749,56.261 170.749,49.542 171.335,48.956 176.21,48.956 177.353,48.956 177.417,48.893 177.607,48.702 ; Q2.2@179.187,49.321 Q2.2@179.512,49.321 ; C102.1@193.128,62.392 192.655,61.92 192.655,49.324 193.241,48.738 195.006,48.738 ; 196.276,48.575 196.113,48.738 196.058,48.738 195.006,48.738 ; 196.403,47.686 196.058,47.686 195.895,47.849 195.006,48.738 ; Q4.2@197.983,49.321 Q4.2@198.308,49.321 ; C103.1@212.913,62.545 211.963,62.545 211.389,61.971 211.389,49.161 211.975,48.575 214.056,48.575 ; 214.945,48.575 214.056,48.575 ; 215.453,47.559 215.072,47.559 214.945,47.686 214.056,48.575 ; Q6.2@216.525,49.321 Q6.2@216.85,49.321
  TOP w1.27: IC8.23@121.503,36.196 121.524,36.217 122.655,36.217 pad.@122.655,38.475 121.503,38.475 IC8.23@121.503,36.196
  TOP w2.54: D3.2@56.658,90.694 56.703,90.739 pad.@58.989,90.739 ; BYQ.2@73.162,91.145 73.162,93.99 81.341,102.169 81.341,108.519 89.055,116.233 EC2.1@94.295,116.233 ; pad.@109.527,119.614 pad.@109.527,118.469 109.527,111.07 R63.2@113.726,106.871
  BOTTOM w0.254: EC2.1@94.295,116.233 EC2.1@94.545,116.233 ; 125.41,120.965 122.362,117.917 100.264,117.917 96.327,113.98 91.501,113.98 90.993,114.488 90.993,119.949 96.2,125.156 114.996,125.156 121.473,131.633 127.661,131.633 127.661,131.628 ; 127.661,121.508 127.661,131.628 ; EC1.1@129.982,123.886 130.196,123.672 132.863,123.672 ; 137.602,120.965 139.507,120.965 141.539,120.965 144.079,120.965 145.349,120.965 ; 161.859,92.644 161.224,92.644 160.716,92.644 160.208,92.644 147.127,105.725 147.127,106.233 147.127,107.059 147.127,108.964 147.127,111.44 147.127,113.345 147.127,115.377 147.127,117.917 147.127,119.187 145.349,120.965 ; pad.@162.875,55.306 162.875,91.628 ; 167.447,94.549 168.32,93.676 168.32,92.66 ; pad.@168.082,51.877 168.171,51.877 168.32,52.026 pad.@168.32,60.526 168.32,92.66 ; 174.808,131.628 127.661,131.628 ; 194.088,133.255 186.468,133.255 179.004,125.791 162.875,125.791 158.049,120.965 ; 145.349,120.965 158.049,120.965 ; 158.049,120.965 153.096,116.012 153.096,107.884 168.32,92.66
  BOTTOM w0.762: 161.859,92.644 162.621,92.644 162.875,92.39
  BOTTOM w2: 135.189,123.378 137.602,120.965 144.016,114.552 ; 144.079,120.965 147.127,117.917 148.524,116.52 148.524,113.98 ; 148.016,112.456 147.127,113.345 144.016,116.457 ; 148.143,110.297 148.143,110.424 147.127,111.44 144.016,114.552 ; 148.524,113.472 148.524,113.98 ; 160.716,95.375 160.716,92.644 147.953,105.408 ; Q2.2@178.916,49.303 Q2.2@179.932,49.303 ; Q4.2@197.775,49.316 Q4.2@198.791,49.316 ; Q6.2@216.35,49.282 Q6.2@217.366,49.282 ; 144.016,110.043 144.143,110.043 ; 144.016,110.043 144.016,112.075 ; 144.016,110.043 144.016,109.345 147.127,106.233 147.953,105.408 ; 144.016,112.075 146.048,110.043 ; 144.016,112.075 144.016,114.552 ; 144.016,114.552 144.016,116.457 ; 144.016,116.457 139.507,120.965 138.364,122.108 138.364,122.997 139.507,122.997 141.539,120.965 147.127,115.377 148.524,113.98 ; 144.143,110.043 147.127,107.059 148.365,105.82 ; 144.143,110.043 146.048,110.043 ; 146.048,110.043 147.127,108.964 148.365,107.725 148.365,105.82 ; 147.953,105.408 148.365,105.82
  BOTTOM w2.286: pad.@122.068,38.561 122.068,40.193 123.407,41.532 132.961,41.532 136.205,38.288 145.476,38.288 161.224,54.036 161.224,92.644 161.224,93.406 161.351,93.533
  BOTTOM w2.54: pad.@58.735,90.739 60.823,92.827 71.455,92.827 73.162,91.12 BYQ.2@73.162,90.891
VDC_AD: C37.2 D13.1 IC11.19 pad.@104.936,82.599 R65.1 R66.2 TP11.1 | length 43.8
  TOP w0.254: D13.1@101.915,88.199 102.015,88.099 102.788,87.326 102.788,87.123 103.947,85.964 R66.2@105.598,84.313 105.722,84.189 R66.2@105.471,83.938 ; pad.@104.936,82.599 105.033,82.502 105.199,82.502 106.218,81.483 106.345,81.483 C37.2@106.868,80.96 ; C37.2@106.805,80.897 106.36,80.452 106.36,78.42 106.868,77.912 110.678,77.912 111.484,77.106 IC11.19@113.387,77.106
  TOP w0.3: TP11.1@112.075,93.406 TP11.1@112.306,93.175 ; R65.1@118.96,98.861 R65.1@119.06,98.861
  TOP w0.5: pad.@104.936,82.599 104.936,83.65 105.223,83.938 R66.2@105.471,83.938 ; TP11.1@112.075,93.406 113.505,93.406 R65.1@118.96,98.861
  BOTTOM w0.5: pad.@104.936,82.599 104.936,84.488 112.035,91.588 TP11.1@112.035,93.406
VOUT3: C42.2 C43.2 IC11.57 | length 10.8
  TOP w0.254: IC11.57@124.987,74.606 126.741,74.606 129.347,77.212 129.347,78.547 130.041,79.24 130.371,79.24 C42.2@130.871,79.741 C43.2@132.903,79.741
VOUT15: C40.2 C41.2 IC11.58 | length 16.6
  TOP w0.254: IC11.58@124.987,75.106 126.631,75.106 128.915,77.39 128.915,79.893 129.982,80.96 133.843,80.96 C40.2@135.062,79.741 C41.2@137.221,79.741
X1: C44.1 IC11.61 Y1.1 | length 19.9
  TOP w0.254: IC11.61@124.987,76.606 126.909,76.606 127.95,77.647 127.95,80.15 128.839,81.039 128.839,82.48 130.113,83.754 132.649,83.754 133.458,84.563 134.711,84.563 135.484,85.336 Y1.1@135.484,85.786 135.189,86.081 C44.1@135.189,88.707
X2: C45.1 IC11.62 Y1.2 | length 15.9
  TOP w0.254: IC11.62@124.987,77.106 126.798,77.106 127.442,77.75 127.442,80.452 128.407,81.417 128.407,82.659 131.084,85.336 Y1.2@131.084,85.786 131.084,86.236 131.857,87.009 132.673,87.825 132.673,88.528 C45.1@132.852,88.707
pads on no net: BYQ.3 BYQ.6 CN1.2 CN10.2 CN10.4 IC8.1 IC8.2 IC8.3 IC8.17 IC8.18 IC8.19 IC9.15 IC15.1

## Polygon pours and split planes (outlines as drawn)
AC_L_F on TOP "TOP16" (solid, pour order 41): 43.495,124.267 43.495,133.157 33.081,143.571 33.081,160.462 32.954,160.589 32.954,169.987 38.282,169.987 39.831,168.438 39.831,146.473 52.766,133.538 52.766,125.664 51.369,124.267
AC_L_F on TOP "TOP15" (solid, pour order 40): 32.954,160.589 24.699,168.844 24.699,171.765 28.382,175.448 28.382,178.369 29.144,179.131 32.954,179.131 34.097,177.988 34.097,161.732
NetBG1_4 on TOP "TOP14" (solid, pour order 39): 18 vertices, not listed, extent 147.254,141.92 213.548,155.382
NetBG1_1 on TOP "TOP13" (solid, pour order 38): 107.503,164.018 106.614,164.907 106.614,170.368 107.376,171.13 169.987,171.13 177.988,179.131 213.675,179.131 215.326,177.48 215.326,168.209 214.437,167.32 181.671,167.32 178.369,164.018
NetD2_1 on TOP "TOP12" (solid, pour order 37): 29 vertices, not listed, extent 187.767,113.197 204.531,141.031
NetC54_1 on TOP "TOP11" (solid, pour order 36): 151.932,35.642 151.255,36.32 151.255,39.451 151.742,39.939 158.938,39.939 159.764,39.114 159.764,36.447 158.959,35.642
NetC60_1 on TOP "TOP10" (solid, pour order 35): 152.461,27.874 151.572,28.763 151.572,33.208 152.334,33.97 158.557,33.97 159.446,33.081 159.446,28.636 158.684,27.874
GND on TOP "TOP9" (solid, pour order 34): 165.463,70.546 155.636,70.546 153.223,72.959 151.354,72.959 151.335,72.978 146.504,77.392 146.504,83.385 147.254,84.135 158.557,84.135 159.319,83.373 159.319,76.896 161.859,74.356 164.526,74.356 165.463,73.419
GND on TOP "TOP8" (solid, pour order 33): 160.589,102.55 125.664,102.55 120.33,107.884 120.33,114.488 121.981,116.139 137.763,116.139 138.271,115.631 155.069,115.631 155.093,115.607 161.121,115.607 163.764,112.964 163.764,105.725
VBB on TOP "TOP7" (solid, pour order 32): 32 vertices, not listed, extent 162.875,39.558 220.025,57.636
NetC75_1 on TOP "TOP6" (solid, pour order 31): 152.461,20.762 151.699,21.524 151.699,25.207 152.588,26.096 158.684,26.096 159.573,25.207 159.573,21.651 158.684,20.762
AC-N-IN on TOP "TOP5" (solid, pour order 30): 20.843,121.6 20.843,147.716 21.905,148.778 27.112,148.778 27.62,148.27 27.62,141.158 25.588,139.126 25.588,122.665 24.367,122.665 23.302,121.6
NetBG1_4 on TOP "TOP4" (solid, pour order 29): 160.97,117.917 145.984,117.917 143.063,120.838 143.063,152.969 145.476,155.382 158.557,155.382 158.557,145.857 158.684,145.73 157.922,144.968 157.922,127.696 161.605,124.013 161.605,118.552
NetC2_1 on TOP "TOP3" (solid, pour order 28): 81.913,138.427 77.023,143.317 77.023,147.127 79.436,149.54 91.374,149.54 92.39,148.524 92.39,145.577 86.828,140.015 83.5,140.015
NetAC-L_1 on TOP "TOP2" (solid, pour order 27): 35.462,124.14 34.097,125.505 34.097,134.808 34.986,135.697 38.161,135.697 41.59,132.268 41.59,124.876 40.854,124.14
NetC2_1 on TOP "TOP1" (solid, pour order 26): 45.146,110.424 42.86,112.71 42.987,112.837 42.987,118.679 42.95,118.769 44.638,120.457 54.139,120.457 63.664,129.982 67.879,129.982 69.657,128.204 69.657,126.045 54.036,110.424
AC_L_F on BOTTOM "BOTTOM40" (solid, pour order 25): 44.257,125.664 43.495,126.426 43.495,133.538 44.511,134.554 51.877,134.554 52.893,133.538 52.893,126.68 51.877,125.664
AC_L_F on BOTTOM "BOTTOM39" (solid, pour order 24): 28.89,164.399 24.572,168.717 24.572,171.892 28.255,175.575 28.255,178.357 29.017,179.119 29.017,179.258 33.208,179.258 34.605,177.861 34.605,170.368 34.923,170.05 38.225,170.05 39.812,168.463 39.812,165.161 39.05,164.399
AC_N on BOTTOM "BOTTOM38" (solid, pour order 23): 199.832,157.795 184.084,173.543 99.756,173.543 92.507,166.294 92.39,166.343 92.39,167.955 89.596,170.749 98.105,179.258 188.783,179.258 202.753,165.288 213.675,165.288 214.945,164.018 214.945,159.192 213.548,157.795
NetBG1_1 on BOTTOM "BOTTOM37" (solid, pour order 22): 106.487,166.431 106.487,170.407 107.337,171.257 112.075,171.257 112.075,166.431
NetD2_1 on BOTTOM "BOTTOM36" (solid, pour order 21): 28 vertices, not listed, extent 188.365,113.179 204.531,143.317
VBB on BOTTOM "BOTTOM35" (solid, pour order 20): 128.038,120.965 127.661,121.342 127.661,131.628 174.808,131.628 177.607,134.427 193.736,134.427 194.625,133.538 194.625,131.633 193.736,130.744 183.957,130.744 179.004,125.791 162.875,125.791 158.049,120.965
AC_N on BOTTOM "BOTTOM34" (solid, pour order 19): 82.992,170.749 82.992,178.369 83.881,179.258 98.105,179.258 98.105,178.877 89.977,170.749
AC_L on BOTTOM "BOTTOM33" (solid, pour order 18): 26 vertices, not listed, extent 93.914,137.602 215.58,161.351
AC_L on BOTTOM "BOTTOM32" (solid, pour order 17): 72.197,110.17 70.292,112.075 70.292,120.582 85.28,135.57 88.707,135.57 93.914,140.777 101.153,140.777 101.407,140.523 101.407,137.602 84.135,120.33 84.135,113.853 80.452,110.17
NetC54_1 on BOTTOM "BOTTOM31" (solid, pour order 16): 151.869,35.705 151.191,36.383 151.191,39.304 151.89,40.003 158.875,40.002 159.7,39.177 159.7,36.51 158.895,35.705
NetC60_1 on BOTTOM "BOTTOM30" (solid, pour order 15): 158.684,27.874 152.461,27.874 151.572,28.763 151.572,33.208 152.334,33.97 158.557,33.97 159.446,33.081 159.446,28.636
NetD2_1 on BOTTOM "BOTTOM29" (solid, pour order 14): 17 vertices, not listed, extent 106.868,136.459 196.276,148.905
NetBG1_1 on BOTTOM "BOTTOM28" (solid, pour order 13): 214.437,167.32 208.341,167.32 206.944,168.717 206.944,175.194 207.579,175.829 214.437,175.829 215.326,174.94 215.326,168.209
NetC75_1 on BOTTOM "BOTTOM27" (solid, pour order 12): 152.461,20.762 151.699,21.524 151.699,25.207 152.588,26.096 158.684,26.096 159.573,25.207 159.573,21.651 158.684,20.762
GND on BOTTOM "BOTTOM26" (solid, pour order 11): 161.447,107.376 158.684,110.256 158.684,114.234 160.716,116.266 172.527,116.266 175.702,119.441 180.655,119.441 184.719,123.505 192.974,123.505 193.609,122.87 193.609,119.441 193.117,118.949 186.005,118.949 174.432,107.376
VBB on BOTTOM "BOTTOM25" (solid, pour order 10): 168.246,51.75 163.399,51.75 162.748,52.401 162.748,92.845 160.007,92.845 147.016,105.836 147.016,119.298 144.323,121.991 144.372,122.108 159.026,122.108 159.075,121.991 153.112,116.028 153.112,109.027 168.336,93.803 168.336,51.84
GND on BOTTOM "BOTTOM24" (solid, pour order 9): 152.745,73.594 146.619,79.72 146.619,88.58 133.284,101.915 132.107,101.915 132.019,102.007 132.829,116.065 133.21,116.065 133.284,116.139 136.713,112.71 136.713,107.503 155.255,88.961 155.255,73.594
AC-N-IN on BOTTOM "BOTTOM23" (solid, pour order 8): 23 vertices, not listed, extent 20.889,122.616 52.131,161.351
NetBG1_1 on BOTTOM "BOTTOM22" (solid, pour order 7): 124.775,166.558 124.775,171.162 137.856,171.162 137.856,166.558
AC_N on BOTTOM "BOTTOM21" (solid, pour order 6): 65.212,143.317 64.577,143.952 64.577,148.27 74.356,158.049 74.356,170.241 74.864,170.749 92.241,170.749 92.39,170.6 92.39,166.177 69.53,143.317
VBB on BOTTOM "BOTTOM20" (solid, pour order 5): 91.501,113.98 90.993,114.488 90.993,119.949 96.2,125.156 114.996,125.156 121.473,131.633 127.661,131.633 127.661,121.508 128.087,121.082 128.038,120.965 125.41,120.965 122.362,117.917 100.264,117.917 96.327,113.98
GND on BOTTOM "BOTTOM19" (solid, pour order 4): 88.326,99.883 87.945,100.264 87.945,107.376 89.342,108.773 101.026,108.773 104.328,112.075 124.267,112.075 128.331,116.139 128.405,116.065 132.829,116.065 132.829,102.878 132.903,102.804 132.014,101.915 97.089,101.915 95.057,99.883
NetC2_1 on BOTTOM "BOTTOM18" (solid, pour order 3): 45.146,110.551 42.987,112.71 42.987,118.679 44.638,120.33 54.163,120.33 77.15,143.317 77.15,147.127 79.436,149.413 91.374,149.413 92.263,148.524 92.263,145.603 86.802,140.142 83.395,140.142 53.804,110.551
NetAC-L_1 on BOTTOM "BOTTOM17" (solid, pour order 2): 35.494,124.267 34.224,125.537 34.224,133.919 36.891,136.586 40.618,136.586 41.485,135.719 41.485,124.924 40.828,124.267
no net on Top Overlay "TOPOVERLAY47" (solid, pour order 0): 78.509,26.985 77.823,28.128 79.195,28.128
no net on Top Overlay "TOPOVERLAY46" (solid, pour order 0): 42.225,26.985 41.539,28.128 42.911,28.128
no net on Top Overlay "TOPOVERLAY45" (solid, pour order 0): 60.551,26.985 59.865,28.128 61.237,28.128
no net on Top Overlay "TOPOVERLAY44" (solid, pour order 0): 55.344,26.985 54.658,28.128 56.03,28.128
no net on Top Overlay "TOPOVERLAY43" (solid, pour order 0): 78.99,41.358 78.304,42.501 79.676,42.501
no net on Top Overlay "TOPOVERLAY42" (solid, pour order 0): 90.538,67.607 90.538,68.979 91.681,68.293
no net on Top Overlay "TOPOVERLAY41" (solid, pour order 0): 27.874,38.491 26.731,39.177 27.874,39.863
no net on Bottom Solder "BOTTOMSOLDER421" (solid, pour order 0): 160.081,64.831 160.081,70.419 162.367,70.419 162.367,64.831
no net on Bottom Solder "BOTTOMSOLDER420" (solid, pour order 0): 160.081,70.673 160.081,76.261 162.367,76.261 162.367,70.673
no net on Bottom Solder "BOTTOMSOLDER419" (solid, pour order 0): 160.081,83.5 160.081,89.088 162.367,89.088 162.367,83.5
no net on Bottom Solder "BOTTOMSOLDER418" (solid, pour order 0): 160.081,76.896 160.081,82.484 162.367,82.484 162.367,76.896
no net on Bottom Solder "BOTTOMSOLDER417" (solid, pour order 0): 162.952,60.59 162.952,66.178 165.492,66.178 165.492,60.59
no net on Bottom Solder "BOTTOMSOLDER416" (solid, pour order 0): 34.478,128.758 34.478,130.952 35.726,130.952 35.726,128.758
no net on Bottom Solder "BOTTOMSOLDER415" (solid, pour order 0): 40.147,127.143 40.147,129.336 41.394,129.336 41.394,127.143
no net on Bottom Solder "BOTTOMSOLDER414" (solid, pour order 0): 40.205,133.059 40.205,135.252 41.453,135.252 41.453,133.059
no net on Bottom Solder "BOTTOMSOLDER413" (solid, pour order 0): 40.059,129.954 40.059,132.147 41.307,132.147 41.307,129.954
no net on Bottom Solder "BOTTOMSOLDER412" (solid, pour order 0): 125.688,102.494 125.688,105.034 133.284,105.034 133.284,102.494
no net on Bottom Solder "BOTTOMSOLDER411" (solid, pour order 0): 165.804,55.687 165.804,58.82 168.344,58.82 168.344,55.687
no net on Bottom Solder "BOTTOMSOLDER410" (solid, pour order 0): 163.01,55.179 163.01,58.82 165.55,58.82 165.55,55.179
no net on Bottom Solder "BOTTOMSOLDER409" (solid, pour order 0): 165.816,59.215 165.816,64.803 168.356,64.803 168.356,59.215
no net on Bottom Solder "BOTTOMSOLDER408" (solid, pour order 0): 162.952,59.193 162.952,64.781 165.492,64.781 165.492,59.193
no net on Bottom Solder "BOTTOMSOLDER407" (solid, pour order 0): 165.816,65.227 165.816,70.815 168.356,70.815 168.356,65.227
no net on Bottom Solder "BOTTOMSOLDER406" (solid, pour order 0): 162.974,65.271 162.974,70.859 165.514,70.859 165.514,65.271
no net on Bottom Solder "BOTTOMSOLDER405" (solid, pour order 0): 165.816,71.218 165.816,76.806 168.356,76.806 168.356,71.218
no net on Bottom Solder "BOTTOMSOLDER404" (solid, pour order 0): 162.93,71.261 162.93,76.849 165.47,76.849 165.47,71.261
no net on Bottom Solder "BOTTOMSOLDER403" (solid, pour order 0): 165.707,80.247 165.707,85.835 168.247,85.835 168.247,80.247
no net on Bottom Solder "BOTTOMSOLDER402" (solid, pour order 0): 165.669,86.294 165.669,91.882 168.209,91.882 168.209,86.294
no net on Bottom Solder "BOTTOMSOLDER401" (solid, pour order 0): 162.875,85.024 162.875,90.612 165.415,90.612 165.415,85.024
no net on Bottom Solder "BOTTOMSOLDER400" (solid, pour order 0): 167.112,111.335 167.112,112.583 169.306,112.583 169.306,111.335
no net on Bottom Solder "BOTTOMSOLDER399" (solid, pour order 0): 167.239,109.557 167.239,110.805 169.433,110.805 169.433,109.557
no net on Bottom Solder "BOTTOMSOLDER398" (solid, pour order 0): 167.239,108.033 167.239,109.281 169.433,109.281 169.433,108.033
no net on Bottom Solder "BOTTOMSOLDER397" (solid, pour order 0): 164.188,108.022 164.188,109.269 166.381,109.269 166.381,108.022
no net on Bottom Solder "BOTTOMSOLDER396" (solid, pour order 0): 164.213,109.416 164.213,110.663 166.407,110.663 166.407,109.416
no net on Bottom Solder "BOTTOMSOLDER395" (solid, pour order 0): 164.191,110.805 164.191,112.053 166.385,112.053 166.385,110.805
no net on Bottom Solder "BOTTOMSOLDER394" (solid, pour order 0): 91.82,118.594 91.82,120.787 93.068,120.787 93.068,118.594
no net on Bottom Solder "BOTTOMSOLDER393" (solid, pour order 0): 93.29,119.822 93.29,122.015 94.538,122.015 94.538,119.822
no net on Bottom Solder "BOTTOMSOLDER392" (solid, pour order 0): 94.709,120.315 94.709,122.509 95.956,122.509 95.956,120.315
no net on Bottom Solder "BOTTOMSOLDER391" (solid, pour order 0): 110.868,144.202 110.868,145.449 113.061,145.449 113.061,144.202
no net on Bottom Solder "BOTTOMSOLDER390" (solid, pour order 0): 113.277,144.174 113.277,145.421 115.47,145.421 115.47,144.174
no net on Bottom Solder "BOTTOMSOLDER389" (solid, pour order 0): 115.515,142.782 115.515,144.03 117.709,144.03 117.709,142.782
no net on Bottom Solder "BOTTOMSOLDER388" (solid, pour order 0): 113.14,142.788 113.14,144.036 115.333,144.036 115.333,142.788
no net on Bottom Solder "BOTTOMSOLDER387" (solid, pour order 0): 110.524,142.839 110.524,144.086 112.717,144.086 112.717,142.839
no net on Bottom Solder "BOTTOMSOLDER386" (solid, pour order 0): 107.704,142.792 107.704,144.04 109.898,144.04 109.898,142.792
no net on Bottom Solder "BOTTOMSOLDER385" (solid, pour order 0): 117.836,143.339 117.836,144.587 120.03,144.587 120.03,143.339
no net on Bottom Solder "BOTTOMSOLDER384" (solid, pour order 0): 173.27,110.686 171.873,112.083 175.429,115.639 176.826,114.242
no net on Bottom Solder "BOTTOMSOLDER383" (solid, pour order 0): 181.741,117.609 180.344,119.006 183.9,122.562 185.297,121.165
no net on Bottom Solder "BOTTOMSOLDER382" (solid, pour order 0): 182.497,115.441 181.1,116.838 184.656,120.394 186.053,118.997
no net on Bottom Solder "BOTTOMSOLDER381" (solid, pour order 0): 177.988,112.329 176.591,113.726 180.147,117.282 181.544,115.885
no net on Bottom Solder "BOTTOMSOLDER380" (solid, pour order 0): 173.113,113.804 171.716,115.201 175.624,119.109 177.021,117.712
no net on Bottom Solder "BOTTOMSOLDER379" (solid, pour order 0): 176.845,114.488 175.448,115.885 178.941,119.378 180.338,117.981
no net on Bottom Solder "BOTTOMSOLDER378" (solid, pour order 0): 185.812,120.735 185.812,121.983 188.005,121.983 188.005,120.735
